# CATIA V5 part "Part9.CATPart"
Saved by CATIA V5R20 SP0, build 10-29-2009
Part number: 1DIN7984616_DIN 7984 - M6 x 16 --- 16C
Revision: ANY
Definition: UNKNOWN
Nomenclature: 1DIN7984616_DIN 7984 - M6 x 16 --- 16C
Source: Unknown
Bounding box of the stored display mesh (mm): x 0 to 20, y -5 to 5, z -5 to 5
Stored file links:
  C:\Users\Utente\Desktop\IO LAVORO\3D X SITO CF\CUMSA\3D files PW\pw101630\pw101630_injection\Part9.CATPart
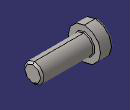
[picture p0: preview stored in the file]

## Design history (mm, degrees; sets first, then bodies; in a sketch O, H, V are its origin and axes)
Body1 "Hex" (main body)
  Solid1: solid without history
